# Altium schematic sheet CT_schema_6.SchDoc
size 284 x 243 mm
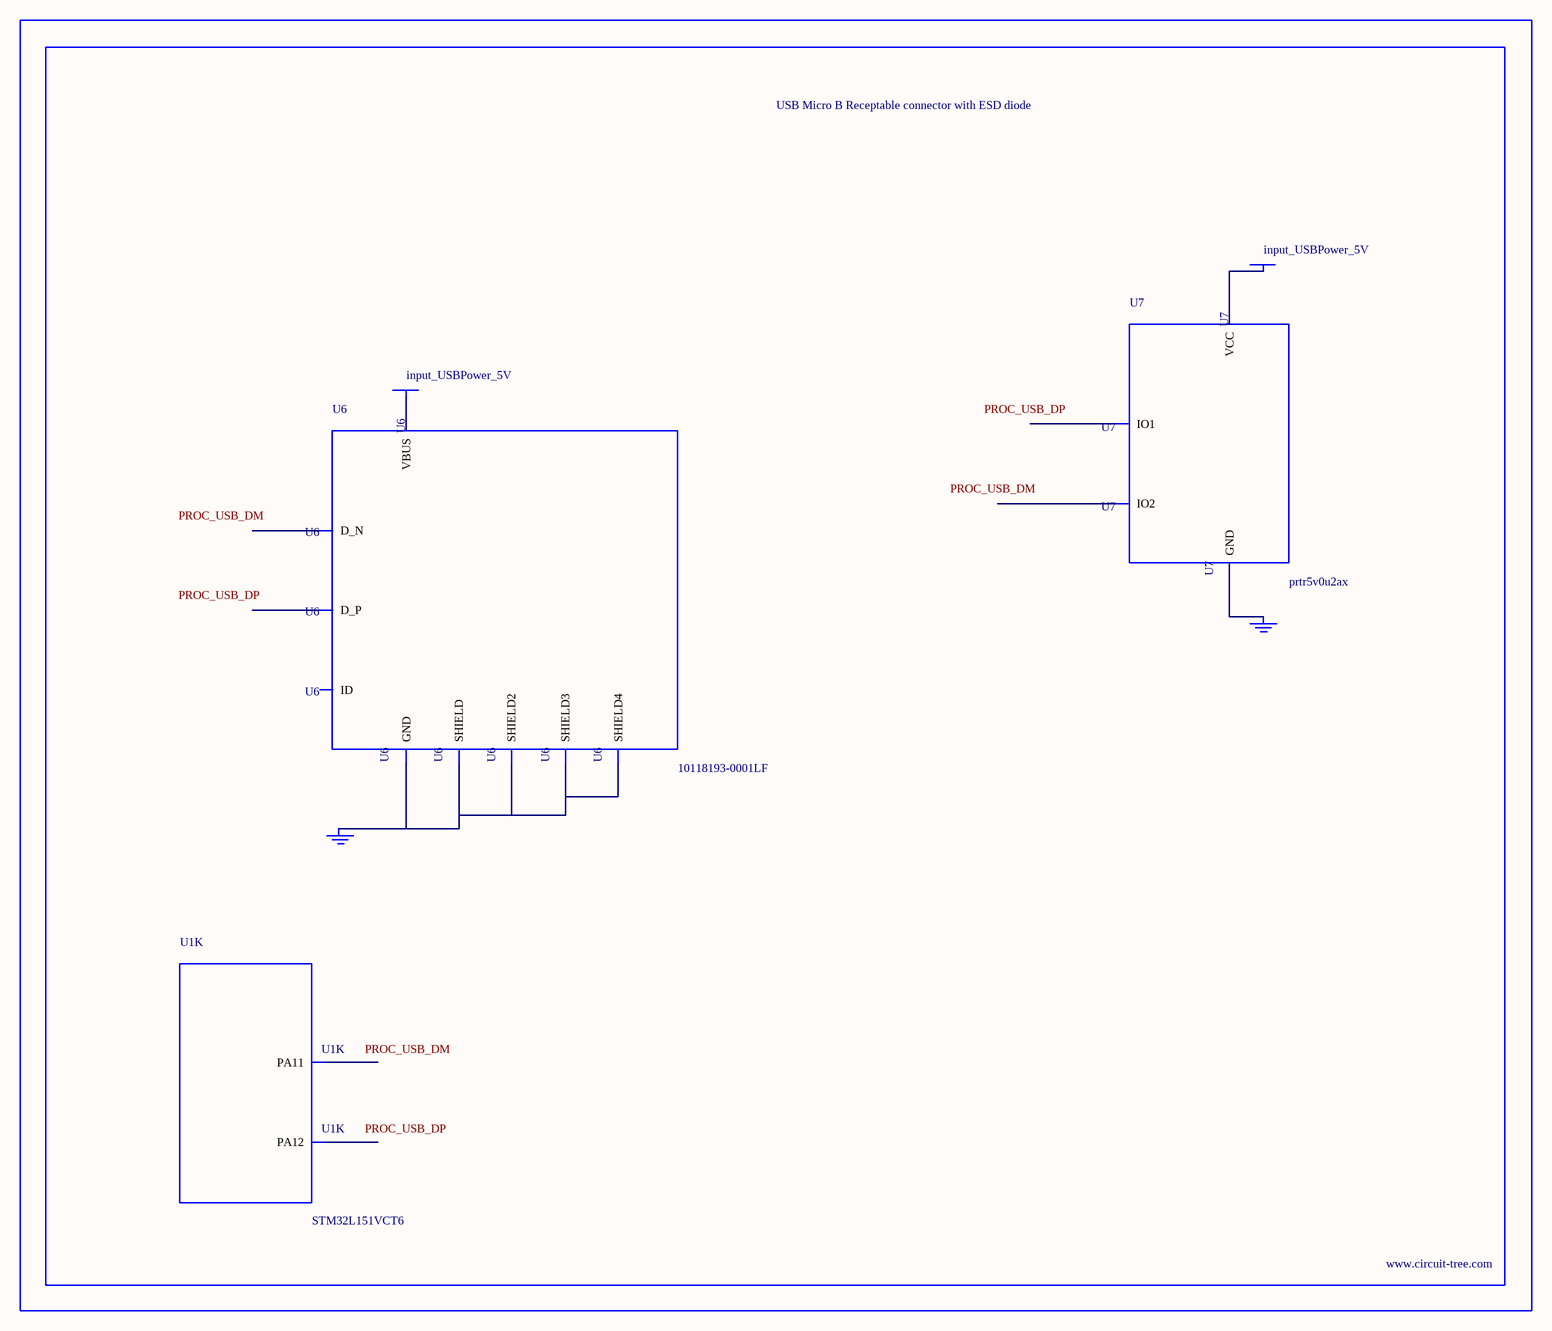
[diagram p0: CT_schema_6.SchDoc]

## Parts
BORDER5  (no value)
GND_INSTANCE_5_0  (no value)
GND_INSTANCE_5_1  (no value)
POWER_INSTANCE_5_0  input_USBPower_5V
POWER_INSTANCE_5_1  input_USBPower_5V
U1  STM32L151VCT6  [LQFP100]  (part K of 11)
U6  10118193-0001LF  [FCI_10118193-0001LF]
U7  prtr5v0u2ax  [SOT143B]

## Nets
NetGND_INSTANCE_5_0_0: GND_INSTANCE_5_0.0(GND) U6.5(GND) U6.6(SHIELD) U6.7(SHIELD2) U6.8(SHIELD3) U6.9(SHIELD4)
NetGND_INSTANCE_5_1_0: GND_INSTANCE_5_1.0(GND) U7.1(GND)
NetPOWER_INSTANCE_5_0_0: POWER_INSTANCE_5_0.0(PWR) U6.1(VBUS)
NetPOWER_INSTANCE_5_1_0: POWER_INSTANCE_5_1.0(PWR) U7.4(VCC)

Not connected (* = marked no-connect by the designer): U1 70(PA11) 71(PA12); U6 2(D_N) 3(D_P) 4(ID); U7 2(IO1) 3(IO2)

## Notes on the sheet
- Labels drawn without touching a wire or pin: PROC_USB_DM, PROC_USB_DP

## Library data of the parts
BORDER5 = BORDER_PAGE5
GND_INSTANCE_5_0 GND_INSTANCE_5_1 = GND
POWER_INSTANCE_5_0 POWER_INSTANCE_5_1 = PWR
